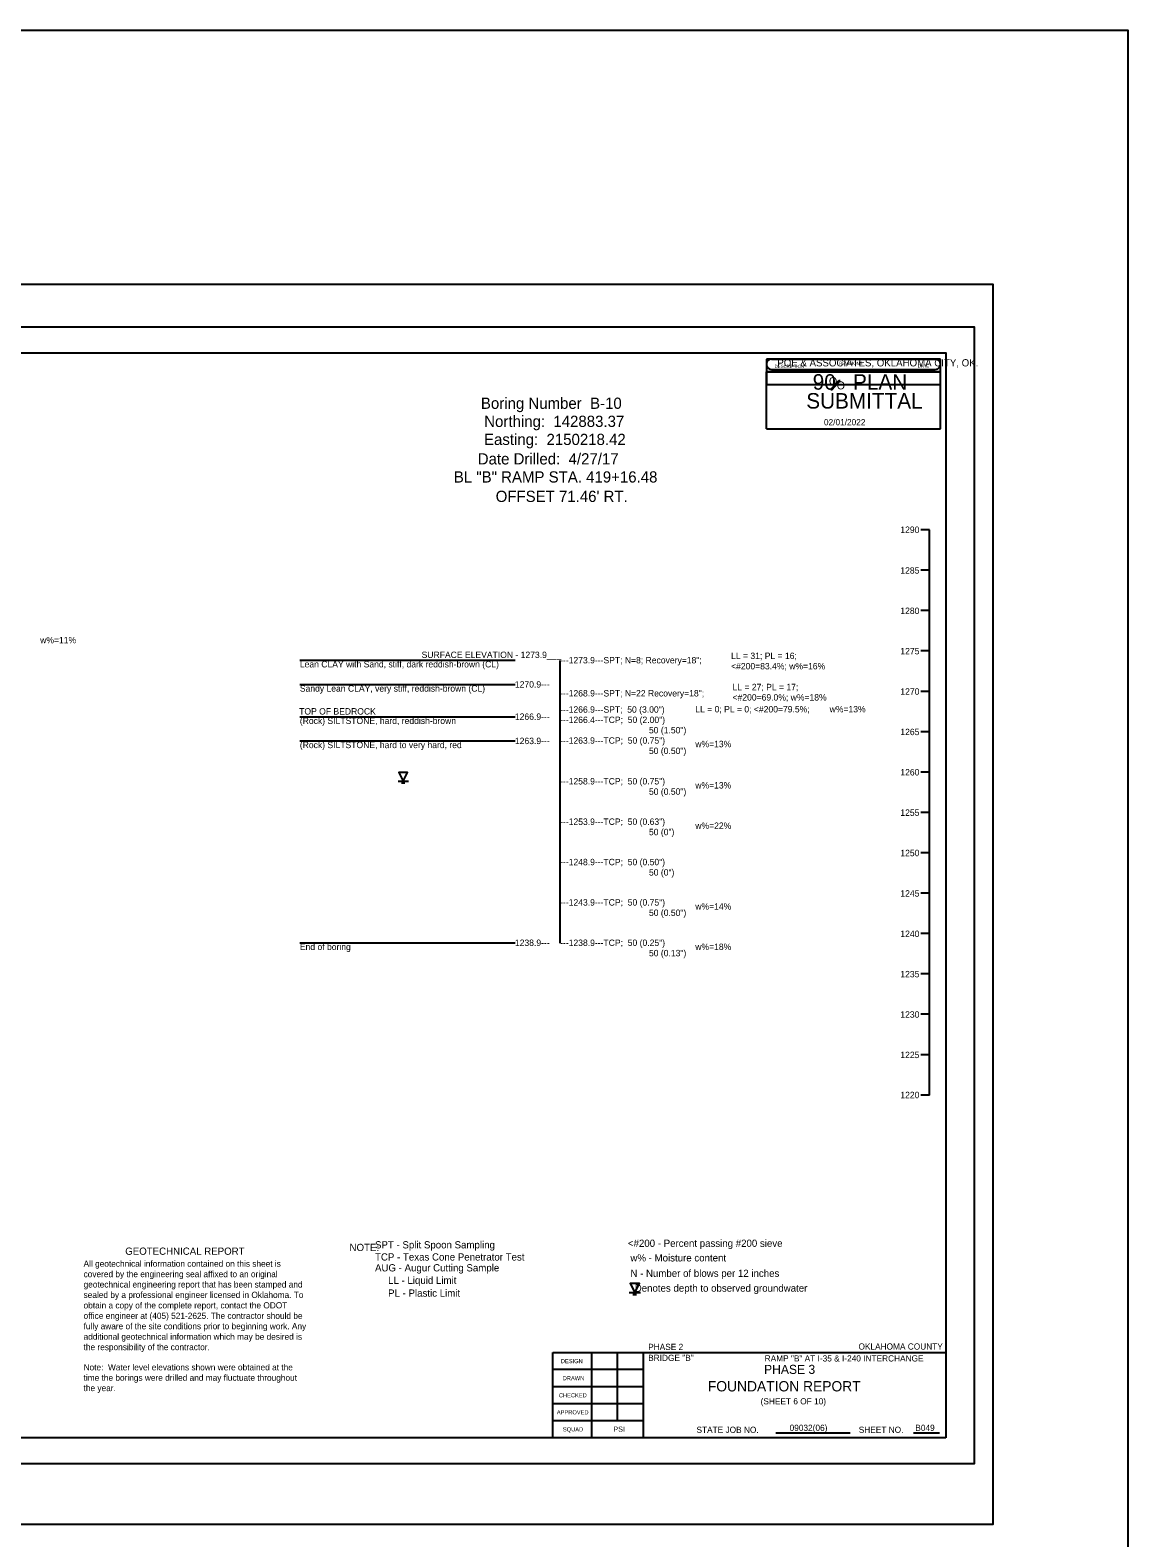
# Model space of a CAD drawing. Extents: x 2150162 to 2150245, y 143729 to 143865.
# Drawn here: x 2150224 to 2150245.24, y 143835.89 to 143865.06 of the extents above; entities that cross this region are included whole.
import ezdxf

# ---------------------------------------------------------------- set-up
doc = ezdxf.new("R2010")
doc.units = 0
for name, color, linetype in [('Default', 7, 'Continuous'), ('S', 7, 'Continuous'), ('SHT_Plot_Shape_Full', 7, 'Continuous'), ('SHT_Plot_Shape_Half', 7, 'Continuous'), ('SHT_Sheet_Border', 7, 'Continuous'), ('SHT_Stamp_90_Submit', 7, 'Continuous'), ('SHT_Stamp_Rev_Block', 7, 'Continuous'), ('SHT_Standard_Sheet_Lines', 7, 'Continuous'), ('SHT_Standard_Sheet_Txt', 7, 'Continuous'), ('T', 7, 'Continuous'), ('T-Title', 7, 'Continuous'), ('Text', 7, 'Continuous')]:
    doc.layers.add(name, color=color, linetype=linetype)

# ---------------------------------------------------------------- blocks, each defined once
blk = doc.blocks.new('DGRFC_WTLEV1')
at = {"layer": 'Default'}
for points in [[(-0.0127, 0), (0.0127, 0)], [(0, 0), (0.0106, 0.0212), (-0.0106, 0.0212), (0, 0)], [(-0.0042, -0.0042), (0.0042, -0.0042)]]:
    blk.add_lwpolyline(points, dxfattribs=at)

msp = doc.modelspace()

# ---------------------------------------------------------------- linework, layer by layer
at = {"layer": 'Default'}
msp.add_line((2150241.402, 143844.453), (2150241.402, 143855.391), dxfattribs=at)
for points in [[(2150241.402, 143855.391), (2150241.235, 143855.391)], [(2150241.402, 143854.61), (2150241.235, 143854.61)], [(2150241.402, 143853.828), (2150241.235, 143853.828)], [(2150241.402, 143853.047), (2150241.235, 143853.047)], [(2150241.402, 143853.047), (2150241.235, 143853.047)], [(2150229.216, 143852.87), (2150233.383, 143852.87)], [(2150234.246, 143852.865), (2150234.246, 143847.395)], [(2150229.216, 143852.401), (2150233.383, 143852.401)], [(2150241.402, 143852.266), (2150241.235, 143852.266)], [(2150229.216, 143851.776), (2150233.383, 143851.776)], [(2150229.216, 143851.307), (2150233.383, 143851.307)], [(2150241.402, 143851.485), (2150241.235, 143851.485)], [(2150241.402, 143850.703), (2150241.235, 143850.703)], [(2150241.402, 143849.922), (2150241.235, 143849.922)], [(2150241.402, 143849.141), (2150241.235, 143849.141)], [(2150241.402, 143848.36), (2150241.235, 143848.36)], [(2150241.402, 143847.578), (2150241.235, 143847.578)], [(2150229.216, 143847.401), (2150233.383, 143847.401)], [(2150241.402, 143846.797), (2150241.235, 143846.797)], [(2150241.402, 143846.016), (2150241.235, 143846.016)], [(2150241.402, 143845.235), (2150241.235, 143845.235)], [(2150241.402, 143844.453), (2150241.235, 143844.453)]]:
    msp.add_lwpolyline(points, dxfattribs=at)
at = {"layer": 'S'}
msp.add_lwpolyline([(2150203.404, 143865.061), (2150245.24, 143865.061), (2150245.24, 143729.315), (2150203.404, 143729.315)], close=True, dxfattribs=at)
at = {"layer": 'SHT_Plot_Shape_Full'}
msp.add_lwpolyline([(2150206.628, 143860.145), (2150242.628, 143860.145), (2150242.628, 143836.145), (2150206.628, 143836.145)], close=True, dxfattribs=at)
at = {"layer": 'SHT_Plot_Shape_Half'}
msp.add_lwpolyline([(2150208.265, 143859.32), (2150242.265, 143859.32), (2150242.265, 143837.32), (2150208.265, 143837.32)], close=True, dxfattribs=at)
at = {"layer": 'SHT_Sheet_Border'}
for p, q in [((2150234.115, 143837.82), (2150234.115, 143839.47)), ((2150234.115, 143839.47), (2150241.715, 143839.47)), ((2150235.865, 143837.82), (2150235.865, 143839.471))]:
    msp.add_line(p, q, dxfattribs=at)
msp.add_lwpolyline([(2150241.715, 143837.82), (2150210.215, 143837.82), (2150210.215, 143858.82), (2150241.715, 143858.82)], close=True, dxfattribs=at)
at = {"layer": 'SHT_Stamp_90_Submit'}
for p, q in [((2150238.346, 143858.696), (2150241.512, 143858.696)), ((2150238.246, 143858.446), (2150241.612, 143858.446)), ((2150238.246, 143857.347), (2150238.246, 143858.446)), ((2150238.346, 143858.496), (2150241.512, 143858.496)), ((2150239.489, 143858.108), (2150239.645, 143858.281)), ((2150239.507, 143858.108), (2150239.662, 143858.281)), ((2150239.512, 143858.108), (2150239.667, 143858.281)), ((2150239.52, 143858.108), (2150239.675, 143858.281)), ((2150239.645, 143858.281), (2150239.675, 143858.281)), ((2150241.612, 143857.347), (2150241.612, 143858.446)), ((2150239.489, 143858.108), (2150239.52, 143858.108)), ((2150238.246, 143857.347), (2150241.612, 143857.347))]:
    msp.add_line(p, q, dxfattribs=at)
for centre, start, end in [((2150238.346, 143858.596), 89.9952, 270), ((2150241.512, 143858.596), 270, 90.0048)]:
    msp.add_arc(centre, 0.1, start, end, dxfattribs=at)
at = {"layer": 'SHT_Stamp_Rev_Block'}
for p, q in [((2150238.246, 143858.696), (2150238.246, 143858.196)), ((2150241.612, 143858.696), (2150238.246, 143858.696)), ((2150241.612, 143858.196), (2150241.612, 143858.696)), ((2150241.612, 143858.446), (2150238.246, 143858.446)), ((2150241.612, 143858.196), (2150238.246, 143858.196))]:
    msp.add_line(p, q, dxfattribs=at)
at = {"layer": 'SHT_Standard_Sheet_Lines'}
for p, q in [((2150234.865, 143837.82), (2150234.865, 143839.471)), ((2150235.365, 143838.15), (2150235.365, 143839.471)), ((2150238.426, 143837.916), (2150239.866, 143837.917)), ((2150241.09, 143837.916), (2150241.593, 143837.917))]:
    msp.add_line(p, q, dxfattribs=at)
for points in [[(2150235.865, 143839.14), (2150234.115, 143839.14)], [(2150235.865, 143838.81), (2150234.115, 143838.81)], [(2150235.865, 143838.48), (2150234.115, 143838.48)], [(2150235.865, 143838.15), (2150234.115, 143838.15)]]:
    msp.add_lwpolyline(points, dxfattribs=at)

# ---------------------------------------------------------------- block references
at = {"layer": 'Default'}
for p, xscale, yscale in [((2150231.216, 143850.526), 7.873999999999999, 7.873999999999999), ((2150235.698, 143840.63), 8.503919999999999, 8.503919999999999)]:
    msp.add_blockref('DGRFC_WTLEV1', p, dxfattribs=dict(at, xscale=xscale, yscale=yscale))

# ---------------------------------------------------------------- texts
for s, height, p in [('Boring Number  B-10', 0.217, (2150232.72, 143857.733)), ('Northing:  142883.37', 0.217, (2150232.784, 143857.383)), ('Easting:  2150218.42', 0.217, (2150232.78, 143857.033)), ('Date Drilled:  4/27/17', 0.217, (2150232.659, 143856.657)), ('BL "B" RAMP STA. 419+16.48', 0.217, (2150232.196, 143856.307)), ("OFFSET 71.46' RT.", 0.217, (2150233.006, 143855.931)), ('1290', 0.124, (2150240.837, 143855.332)), ('1285', 0.124, (2150240.837, 143854.544)), ('1280', 0.124, (2150240.837, 143853.763)), ('w%=11%', 0.124, (2150224.191, 143853.196)), ('SURFACE ELEVATION - 1273.9___', 0.124, (2150231.573, 143852.911)), ('LL = 31; PL = 16;', 0.124, (2150237.562, 143852.891)), ('1275', 0.124, (2150240.837, 143852.982)), ('Lean CLAY with Sand, stiff, dark reddish-brown (CL)', 0.124, (2150229.216, 143852.729)), ('---1273.9---SPT; N=8; Recovery=18";', 0.124, (2150234.253, 143852.807)), ('<#200=83.4%; w%=16%', 0.124, (2150237.562, 143852.691)), ('Sandy Lean CLAY, very stiff, reddish-brown (CL)', 0.124, (2150229.216, 143852.26)), ('1270.9---', 0.124, (2150233.378, 143852.339)), ('LL = 27; PL = 17;', 0.124, (2150237.59, 143852.288)), ('---1268.9---SPT; N=22 Recovery=18";', 0.124, (2150234.253, 143852.167)), ('<#200=69.0%; w%=18%', 0.124, (2150237.59, 143852.088)), ('1270', 0.124, (2150240.837, 143852.201)), ('TOP OF BEDROCK', 0.124, (2150229.203, 143851.817)), ('1266.9---', 0.124, (2150233.378, 143851.714)), ('---1266.9---SPT;  50 (3.00")', 0.124, (2150234.253, 143851.853)), ('LL = 0; PL = 0; <#200=79.5%;', 0.124, (2150236.869, 143851.858)), ('w%=13%', 0.124, (2150239.469, 143851.859)), ('(Rock) SILTSTONE, hard, reddish-brown', 0.124, (2150229.216, 143851.635)), ('---1266.4---TCP;  50 (2.00")', 0.124, (2150234.253, 143851.653)), ('50 (1.50")', 0.124, (2150235.972, 143851.453)), ('1265', 0.124, (2150240.837, 143851.419)), ('(Rock) SILTSTONE, hard to very hard, red', 0.124, (2150229.216, 143851.167)), ('1263.9---', 0.124, (2150233.378, 143851.245)), ('---1263.9---TCP;  50 (0.75")', 0.124, (2150234.253, 143851.253)), ('w%=13%', 0.124, (2150236.869, 143851.185)), ('50 (0.50")', 0.124, (2150235.972, 143851.053)), ('1260', 0.124, (2150240.837, 143850.638)), ('---1258.9---TCP;  50 (0.75")', 0.124, (2150234.253, 143850.464)), ('50 (0.50")', 0.124, (2150235.972, 143850.264)), ('w%=13%', 0.124, (2150236.869, 143850.386)), ('---1253.9---TCP;  50 (0.63")', 0.124, (2150234.253, 143849.682)), ('1255', 0.124, (2150240.837, 143849.857)), ('50 (0")', 0.124, (2150235.972, 143849.482)), ('w%=22%', 0.124, (2150236.869, 143849.604)), ('1250', 0.124, (2150240.837, 143849.076)), ('---1248.9---TCP;  50 (0.50")', 0.124, (2150234.253, 143848.901)), ('50 (0")', 0.124, (2150235.972, 143848.701)), ('1245', 0.124, (2150240.837, 143848.294)), ('---1243.9---TCP;  50 (0.75")', 0.124, (2150234.253, 143848.12)), ('50 (0.50")', 0.124, (2150235.972, 143847.92)), ('w%=14%', 0.124, (2150236.869, 143848.042)), ('1238.9---', 0.124, (2150233.378, 143847.339)), ('---1238.9---TCP;  50 (0.25")', 0.124, (2150234.253, 143847.339)), ('1240', 0.124, (2150240.837, 143847.513)), ('End of boring', 0.124, (2150229.216, 143847.26)), ('50 (0.13")', 0.124, (2150235.972, 143847.139)), ('w%=18%', 0.124, (2150236.869, 143847.261)), ('1235', 0.124, (2150240.837, 143846.732)), ('1230', 0.124, (2150240.837, 143845.951)), ('1225', 0.124, (2150240.837, 143845.169)), ('1220', 0.124, (2150240.837, 143844.393))]:
    msp.add_text(s, height=height, dxfattribs=at).set_placement(p)
at = {"layer": 'Defpoints'}
msp.add_text('PHASE 3', height=0.175, dxfattribs=at).set_placement((2150238.2, 143839.058))
at = {"layer": 'SHT_Stamp_90_Submit'}
for s, height, p in [('POE & ASSOCIATES, OKLAHOMA CITY, OK.', 0.14, (2150238.456, 143858.554)), ('90   PLAN', 0.3, (2150239.141, 143858.104)), ('O', 0.153, (2150239.455, 143858.193)), ('O', 0.153, (2150239.607, 143858.109)), ('SUBMITTAL', 0.3, (2150239.017, 143857.738)), ('02/01/2022', 0.12, (2150239.359, 143857.415))]:
    msp.add_text(s, height=height, dxfattribs=at).set_placement(p)
at = {"layer": 'SHT_Stamp_Rev_Block'}
for s, height, p in [('DESCRIPTION', 0.05999, (2150238.406, 143858.525)), ('REVISIONS', 0.06, (2150239.654, 143858.584)), ('DATE', 0.06, (2150241.175, 143858.529))]:
    msp.add_text(s, height=height, dxfattribs=at).set_placement(p)
at = {"layer": 'SHT_Standard_Sheet_Txt'}
for s, height, p in [('DESIGN', 0.08, (2150234.267, 143839.265)), ('DRAWN', 0.08, (2150234.303, 143838.935)), ('CHECKED', 0.08, (2150234.228, 143838.605)), ('APPROVED', 0.08, (2150234.189, 143838.275)), ('SQUAD', 0.08, (2150234.307, 143837.945)), ('STATE JOB NO.', 0.12, (2150236.892, 143837.916)), ('SHEET NO. ', 0.12, (2150240.032, 143837.917))]:
    msp.add_text(s, height=height, dxfattribs=at).set_placement(p)
at = {"layer": 'T'}
for s, height, p in [('PHASE 2', 0.12, (2150235.957, 143839.52)), ('OKLAHOMA COUNTY', 0.12, (2150240.027, 143839.528)), ('BRIDGE "B"', 0.12, (2150235.957, 143839.308)), ('RAMP "B" AT I-35 & I-240 INTERCHANGE', 0.12, (2150238.212, 143839.298)), ('(SHEET 6 OF 10)', 0.12, (2150238.133, 143838.468)), ('PSI', 0.1, (2150235.284, 143837.938)), ('09032(06)', 0.12, (2150238.694, 143837.955)), ('B049', 0.12, (2150241.127, 143837.955))]:
    msp.add_text(s, height=height, dxfattribs=at).set_placement(p)
at = {"layer": 'T-Title'}
msp.add_text('FOUNDATION REPORT', height=0.2, dxfattribs=at).set_placement((2150237.112, 143838.719))
at = {"layer": 'Text'}
for s, height, p in [('    SPT - Split Spoon Sampling', 0.14, (2150230.463, 143841.486)), (' <#200 - Percent passing #200 sieve', 0.14, (2150235.513, 143841.516)), ('GEOTECHNICAL REPORT', 0.14, (2150225.837, 143841.363)), ('NOTE:', 0.14, (2150230.178, 143841.435)), ('    TCP - Texas Cone Penetrator Test', 0.14, (2150230.463, 143841.251)), ('w% - Moisture content', 0.14, (2150235.613, 143841.234)), ('All geotechnical information contained on this sheet is ', 0.12, (2150225.031, 143841.131)), ('covered by the engineering seal affixed to an original ', 0.12, (2150225.031, 143840.929)), ('    AUG - Augur Cutting Sample', 0.14, (2150230.463, 143841.041)), ('N - Number of blows per 12 inches', 0.14, (2150235.613, 143840.935)), ('geotechnical engineering report that has been stamped and ', 0.12, (2150225.031, 143840.729)), (' LL - Liquid Limit', 0.14, (2150230.872, 143840.799)), ('    Denotes depth to observed groundwater', 0.14, (2150235.489, 143840.648)), ('sealed by a professional engineer licensed in Oklahoma. To ', 0.12, (2150225.031, 143840.527)), ('obtain a copy of the complete report, contact the ODOT ', 0.12, (2150225.031, 143840.325)), (' PL - Plastic Limit', 0.14, (2150230.872, 143840.552)), ('office engineer at (405) 521-2625. The contractor should be ', 0.12, (2150225.031, 143840.123)), ('fully aware of the site conditions prior to beginning work. Any ', 0.12, (2150225.031, 143839.921)), ('additional geotechnical information which may be desired is ', 0.12, (2150225.031, 143839.719)), ('the responsibility of the contractor.', 0.12, (2150225.031, 143839.517)), ('Note:  Water level elevations shown were obtained at the ', 0.12, (2150225.031, 143839.126)), ('time the borings were drilled and may fluctuate throughout ', 0.12, (2150225.031, 143838.924)), ('the year.', 0.12, (2150225.031, 143838.724))]:
    msp.add_text(s, height=height, dxfattribs=at).set_placement(p)

doc.saveas('drawing.dxf')
